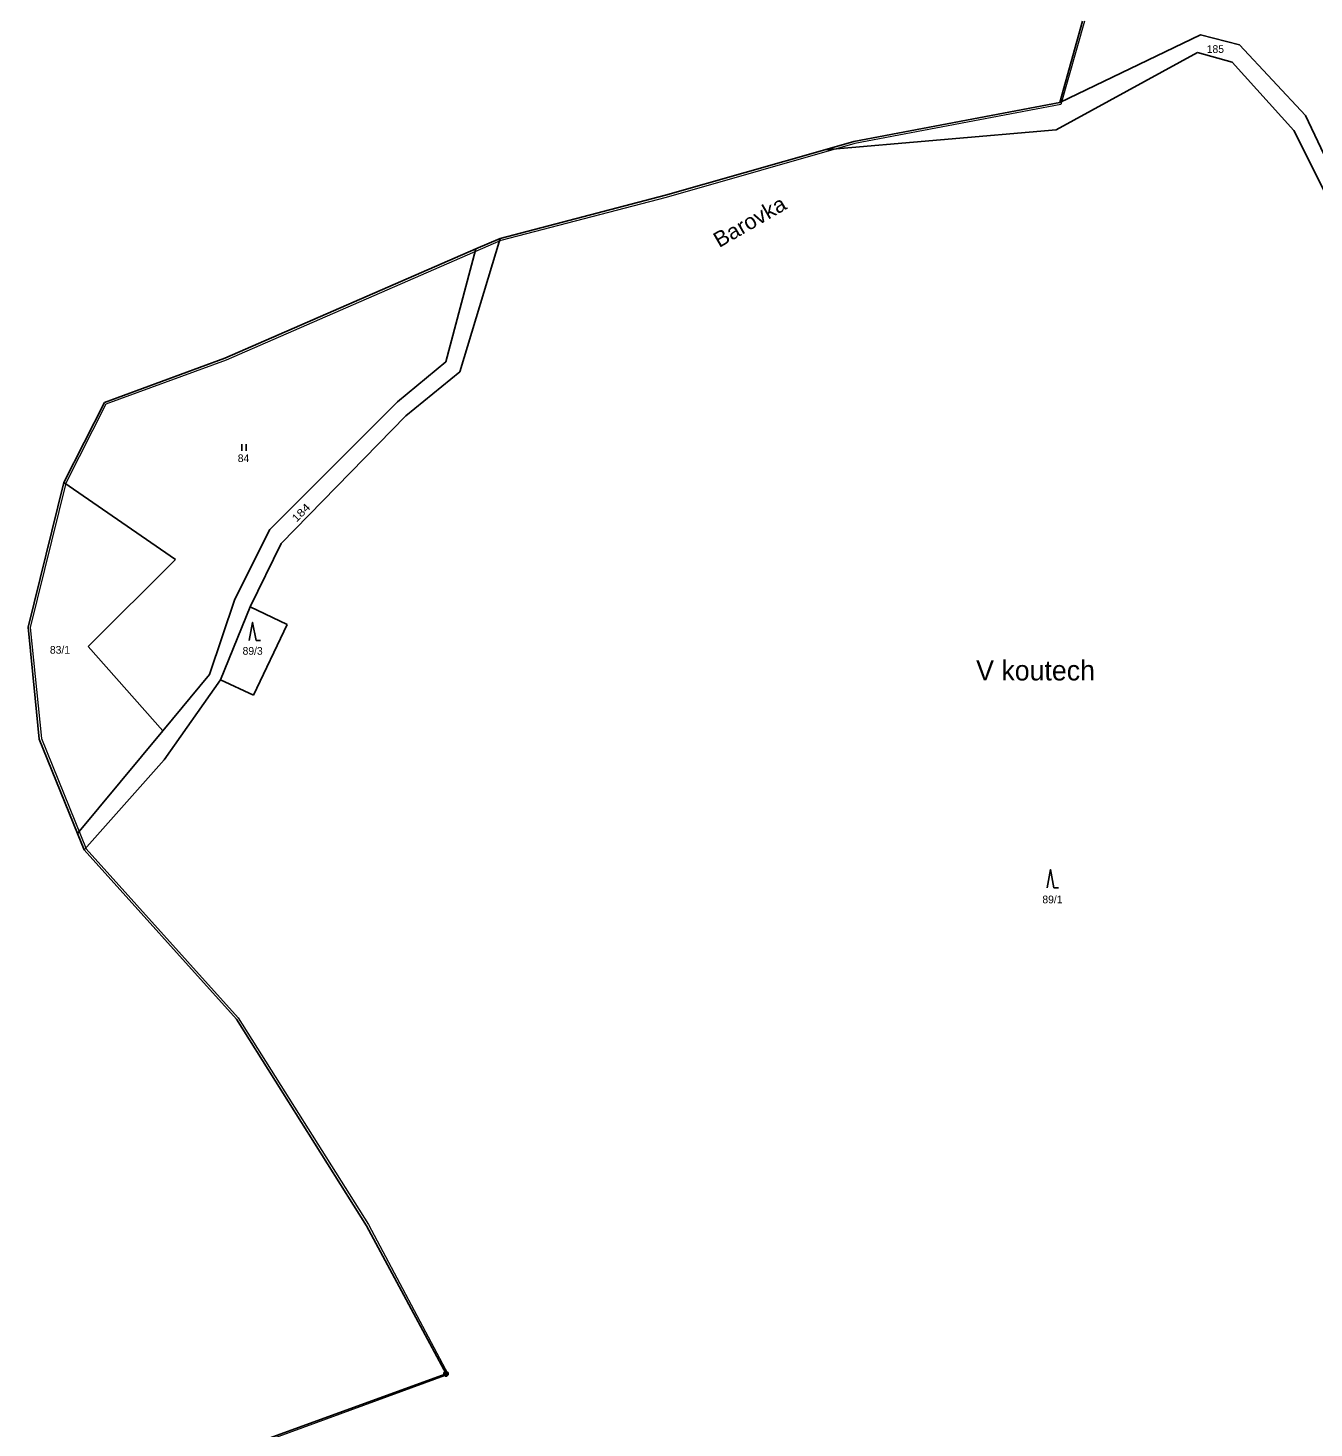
# Model space of a CAD drawing. Extents: x -653193 to -651624, y -1092017 to -1090260.
# Drawn here: x -652904.1 to -652620.8, y -1090861.4 to -1090553 of the extents above; entities that cross this region are included whole.
import ezdxf
from ezdxf.enums import TextEntityAlignment as Align

# ---------------------------------------------------------------- set-up
doc = ezdxf.new("R2010")
doc.units = 0
doc.header["$LTSCALE"] = 0.68
for name, color, linetype, lineweight in [('1', 7, 'Continuous', 25), ('3', 7, 'Continuous', 25), ('4', 7, 'Continuous', 13), ('7', 7, 'Continuous', 13), ('8', 7, 'Continuous', 25)]:
    doc.layers.add(name, color=color, linetype=linetype, lineweight=lineweight)
doc.layers.add('2', color=7, linetype='Continuous')

msp = doc.modelspace()

# ---------------------------------------------------------------- linework, layer by layer
at = {"layer": '1'}
for p, q in [((-652671.8, -1090551.52), (-652676.74, -1090569.4)), ((-652645.79, -1090554.52), (-652676.74, -1090569.4)), ((-652637.16, -1090556.74), (-652645.79, -1090554.52)), ((-652622.63, -1090572.26), (-652637.16, -1090556.74)), ((-652646.47, -1090558.38), (-652677.55, -1090575.43)), ((-652638.79, -1090560.57), (-652646.47, -1090558.38)), ((-652625.22, -1090575.6), (-652638.79, -1090560.57)), ((-652676.74, -1090569.4), (-652722.11, -1090578.01)), ((-652610.85, -1090597.36), (-652622.63, -1090572.26)), ((-652677.55, -1090575.43), (-652728.55, -1090579.85)), ((-652612.33, -1090601.42), (-652625.22, -1090575.6)), ((-652722.11, -1090578.01), (-652728.55, -1090579.85)), ((-652728.55, -1090579.85), (-652763.64, -1090589.86)), ((-652763.64, -1090589.86), (-652800.08, -1090599.38)), ((-652800.08, -1090599.38), (-652808.91, -1090628.73)), ((-652800.08, -1090599.38), (-652805.39, -1090601.69)), ((-652805.39, -1090601.69), (-652860.66, -1090625.76)), ((-652812, -1090626.54), (-652805.39, -1090601.69)), ((-652860.66, -1090625.76), (-652887.17, -1090635.48)), ((-652812, -1090626.54), (-652822.63, -1090635.34)), ((-652808.91, -1090628.73), (-652820.79, -1090638.44)), ((-652887.17, -1090635.48), (-652896.16, -1090653.11)), ((-652850.77, -1090663.49), (-652822.63, -1090635.34)), ((-652820.79, -1090638.44), (-652848.27, -1090666.57)), ((-652896.16, -1090653.11), (-652904.05, -1090685.01)), ((-652896.16, -1090653.11), (-652871.57, -1090670.07)), ((-652850.77, -1090663.49), (-652858.47, -1090678.84)), ((-652848.27, -1090666.57), (-652855.13, -1090680.53)), ((-652890.79, -1090689.28), (-652871.57, -1090670.07)), ((-652864.1, -1090695.4), (-652858.47, -1090678.84)), ((-652855.13, -1090680.53), (-652861.62, -1090696.58)), ((-652855.13, -1090680.53), (-652846.97, -1090684.41)), ((-652854.38, -1090700.01), (-652846.97, -1090684.41)), ((-652902.47, -1090700.67), (-652904.05, -1090685.01)), ((-652874.37, -1090707.8), (-652890.79, -1090689.28)), ((-652874.37, -1090707.8), (-652864.1, -1090695.4)), ((-652874.03, -1090714.21), (-652861.62, -1090696.58)), ((-652861.62, -1090696.58), (-652854.38, -1090700.01)), ((-652901.57, -1090709.66), (-652902.47, -1090700.67)), ((-652893.13, -1090730.45), (-652874.37, -1090707.8)), ((-652901.57, -1090709.66), (-652893.13, -1090730.45)), ((-652891.66, -1090734.07), (-652874.03, -1090714.21)), ((-652893.13, -1090730.45), (-652891.66, -1090734.07)), ((-652891.66, -1090734.07), (-652858.13, -1090771.37)), ((-652858.13, -1090771.37), (-652829.52, -1090816.84)), ((-652829.52, -1090816.84), (-652811.97, -1090849.49)), ((-652811.97, -1090849.49), (-652864.05, -1090868.37))]:
    msp.add_line(p, q, dxfattribs=at)
at = {"layer": '3'}
for p, q in [((-652856.981, -1090646.17), (-652856.981, -1090644.67)), ((-652855.98, -1090646.17), (-652855.98, -1090644.67)), ((-652853.82, -1090687.95), (-652852.824, -1090687.95)), ((-652678.08, -1090742.4), (-652677.084, -1090742.4))]:
    msp.add_line(p, q, dxfattribs=at)
for points in [[(-652853.82, -1090687.95), (-652854.57, -1090683.95), (-652855.32, -1090687.95)], [(-652678.08, -1090742.4), (-652678.83, -1090738.4), (-652679.58, -1090742.4)]]:
    msp.add_lwpolyline(points, dxfattribs=at)
at = {"layer": '4'}
for p, q in [((-652671.3, -1090551.49), (-652676.54, -1090569.86)), ((-652676.54, -1090569.86), (-652721.95, -1090578.48)), ((-652721.95, -1090578.48), (-652763.5, -1090590.34)), ((-652763.5, -1090590.34), (-652799.93, -1090599.86)), ((-652799.93, -1090599.86), (-652860.42, -1090626.2)), ((-652860.42, -1090626.2), (-652886.88, -1090635.89)), ((-652886.88, -1090635.89), (-652895.7, -1090653.3)), ((-652895.7, -1090653.3), (-652903.55, -1090685.05)), ((-652903.55, -1090685.05), (-652901.09, -1090709.51)), ((-652901.09, -1090709.51), (-652891.24, -1090733.79)), ((-652891.24, -1090733.79), (-652857.75, -1090771.04)), ((-652857.75, -1090771.04), (-652829.08, -1090816.6)), ((-652829.08, -1090816.6), (-652811.48, -1090849.6)), ((-652811.48, -1090849.6), (-652863.64, -1090868.66))]:
    msp.add_line(p, q, dxfattribs=at)
at = {"layer": '8'}
for radius in [0.5, 0.0303]:
    msp.add_circle((-652811.97, -1090849.4899), radius, dxfattribs=at)

# ---------------------------------------------------------------- texts
at = {"layer": '2'}
for s, p in [('185', (-652642.509, -1090558.505)), ('84', (-652856.579, -1090648.635)), ('83/1', (-652897.009, -1090690.845)), ('89/3', (-652854.569, -1090691.075)), ('89/1', (-652678.399, -1090745.825))]:
    msp.add_text(s, height=1.7, dxfattribs=at).set_placement(p, align=Align.CENTER)
at = {"layer": '2', "width": 1.2}
msp.add_text('184', height=1.7, rotation=45, dxfattribs=at).set_placement((-652843.3225, -1090660.3835), align=Align.CENTER)
at = {"layer": '7', "width": 1.05}
msp.add_text('Barovka', height=3.4, rotation=30, dxfattribs=at).set_placement((-652744.234, -1090597.1315), align=Align.CENTER)
at = {"layer": '7'}
msp.add_text('V koutech', height=4.4, dxfattribs=at).set_placement((-652682.119, -1090696.73), align=Align.CENTER)

doc.saveas('drawing.dxf')
